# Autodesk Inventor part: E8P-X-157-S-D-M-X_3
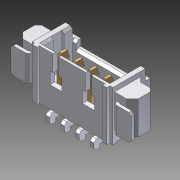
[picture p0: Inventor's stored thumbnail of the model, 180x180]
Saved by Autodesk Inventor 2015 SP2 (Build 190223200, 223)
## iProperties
Created: 2012-07
Part Number: E8P-X-157-S-D-M-X_3
Material: Allgemein
Document SubType Name: Modeling
Designer: rYan
Density: 1 g/cm^3
Mass: 0.0624434 g
Surface Area: 2.40166 cm^2
Volume: 0.0624434 cm^3
Appearance: Vorgabe
Author: rYan
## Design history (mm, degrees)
node "E8P-X-157-S-D-M-X_31"
node "E8P-X-157-S-D-M-X_3"
node "Basis1"
